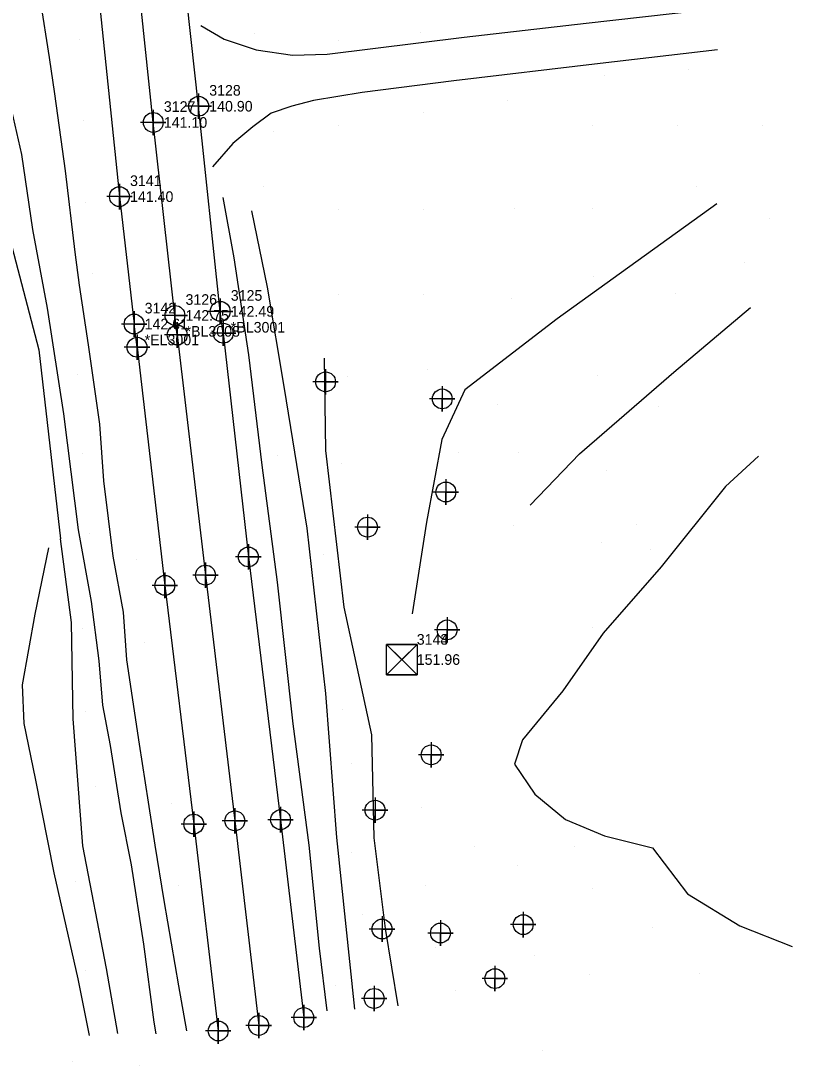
# Model space of a CAD drawing. Extents: x 2312183 to 2312663, y 819676 to 820746.
# Drawn here: x 2312471.4 to 2312653.3, y 819694.7 to 819940.8 of the extents above; entities that cross this region are included whole.
import ezdxf

# ---------------------------------------------------------------- set-up
doc = ezdxf.new("R2010")
doc.units = 0
for name, color, linetype in [('CTL Bench Mark CELL', 7, 'Continuous'), ('CTL Bench Mark Cogo Elevation', 7, 'Continuous'), ('CTL Bench Mark Cogo Number', 7, 'Continuous'), ('Exist DTM Crownline', 7, 'Continuous'), ('Exist DTM Crownline Cogo Comment', 7, 'Continuous'), ('Exist DTM Crownline Cogo Elevation', 7, 'Continuous'), ('Exist DTM Crownline Cogo Number', 7, 'Continuous'), ('Exist DTM Crownline Cogo Point CELL', 7, 'Continuous'), ('Exist DTM Regular Point CELL', 7, 'Continuous'), ('Exist Roads EOP', 7, 'Continuous'), ('Exist Roads EOP Cogo Comment', 7, 'Continuous'), ('Exist Roads EOP Cogo Elevation', 7, 'Continuous'), ('Exist Roads EOP Cogo Number', 7, 'Continuous'), ('Exist Roads EOP Cogo Point CELL', 7, 'Continuous'), ('PH Exist DTM Breakline', 7, 'Continuous'), ('PH Exist DTM Point', 7, 'Continuous')]:
    doc.layers.add(name, color=color, linetype=linetype)

msp = doc.modelspace()

# ---------------------------------------------------------------- linework, layer by layer
at = {"layer": 'CTL Bench Mark CELL'}
for p, q in [((2312561.27, 819790.29), (2312561.27, 819790.29)), ((2312561.27, 819790.29), (2312561.27, 819790.29)), ((2312561.27, 819790.28), (2312561.27, 819790.28)), ((2312561.27, 819790.28), (2312561.27, 819790.28))]:
    msp.add_line(p, q, dxfattribs=at)
for points in [[(2312557.67, 819793.87), (2312564.86, 819793.87), (2312564.86, 819786.69), (2312557.67, 819786.69)], [(2312557.67, 819793.87), (2312564.86, 819793.87), (2312564.86, 819786.68), (2312557.67, 819786.68)], [(2312557.67, 819793.87), (2312564.86, 819793.87), (2312564.86, 819786.69), (2312557.67, 819786.69)], [(2312557.67, 819793.87), (2312564.86, 819793.87), (2312564.86, 819786.68), (2312557.67, 819786.68)]]:
    msp.add_lwpolyline(points, close=True, dxfattribs=at)
for points in [[(2312564.86, 819793.87), (2312557.67, 819786.69), (2312561.26, 819790.28), (2312564.86, 819786.69), (2312557.67, 819793.87)], [(2312561.26, 819790.28), (2312564.86, 819793.87), (2312557.67, 819793.87), (2312561.26, 819790.28)], [(2312564.86, 819793.87), (2312557.67, 819786.68), (2312561.26, 819790.28), (2312564.86, 819786.68), (2312557.67, 819793.87)], [(2312561.26, 819790.28), (2312564.86, 819793.87), (2312557.67, 819793.87), (2312561.26, 819790.28)], [(2312564.86, 819793.87), (2312557.67, 819786.69), (2312561.26, 819790.28), (2312564.86, 819786.69), (2312557.67, 819793.87)], [(2312561.26, 819790.28), (2312564.86, 819793.87), (2312557.67, 819793.87), (2312561.26, 819790.28)], [(2312564.86, 819793.87), (2312557.67, 819786.68), (2312561.26, 819790.28), (2312564.86, 819786.68), (2312557.67, 819793.87)], [(2312561.26, 819790.28), (2312564.86, 819793.87), (2312557.67, 819793.87), (2312561.26, 819790.28)], [(2312561.26, 819790.28), (2312557.67, 819786.69), (2312564.86, 819786.69), (2312561.26, 819790.28)], [(2312561.26, 819790.28), (2312557.67, 819786.68), (2312564.86, 819786.68), (2312561.26, 819790.28)], [(2312561.26, 819790.28), (2312557.67, 819786.69), (2312564.86, 819786.69), (2312561.26, 819790.28)], [(2312561.26, 819790.28), (2312557.67, 819786.68), (2312564.86, 819786.68), (2312561.26, 819790.28)]]:
    msp.add_lwpolyline(points, dxfattribs=at)
at = {"layer": 'Exist DTM Crownline'}
for points in [[(2312507.73, 819871.39), (2312502.62, 819916.87), (2312496.97, 819970.94), (2312491.86, 820021.16), (2312483.41, 820106.75)], [(2312508.27, 819866.79), (2312507.73, 819871.39)], [(2312508.27, 819866.79), (2312514.94, 819810.18), (2312521.86, 819752.27), (2312527.49, 819704.05)]]:
    msp.add_lwpolyline(points, dxfattribs=at)
at = {"layer": 'Exist DTM Crownline Cogo Point CELL'}
for points in [[(2312502.62, 819919.87), (2312502.62, 819913.87), (2312502.62, 819916.87), (2312505.62, 819916.87), (2312499.62, 819916.87)], [(2312502.62, 819919.87), (2312502.62, 819913.87), (2312502.62, 819916.87), (2312505.62, 819916.87), (2312499.62, 819916.87)], [(2312507.73, 819874.39), (2312507.73, 819868.39), (2312507.73, 819871.39), (2312510.73, 819871.39), (2312504.73, 819871.39)], [(2312507.73, 819874.39), (2312507.73, 819868.39), (2312507.73, 819871.39), (2312510.73, 819871.39), (2312504.73, 819871.39)], [(2312508.27, 819869.79), (2312508.27, 819863.79), (2312508.27, 819866.79), (2312511.27, 819866.79), (2312505.27, 819866.79)], [(2312514.94, 819813.18), (2312514.94, 819807.18), (2312514.94, 819810.18), (2312517.94, 819810.18), (2312511.94, 819810.18)], [(2312521.86, 819755.27), (2312521.86, 819749.27), (2312521.86, 819752.27), (2312524.86, 819752.27), (2312518.86, 819752.27)], [(2312527.49, 819707.05), (2312527.49, 819701.05), (2312527.49, 819704.05), (2312530.49, 819704.05), (2312524.49, 819704.05)]]:
    msp.add_lwpolyline(points, dxfattribs=at)
for centre in [(2312502.62, 819916.87), (2312502.62, 819916.87), (2312507.73, 819871.39), (2312507.73, 819871.39), (2312508.27, 819866.79), (2312514.94, 819810.18), (2312521.86, 819752.27), (2312527.49, 819704.05)]:
    msp.add_circle(centre, 2.34, dxfattribs=at)
at = {"layer": 'Exist DTM Regular Point CELL'}
for points in [[(2312543.27, 819858.74), (2312543.27, 819852.74), (2312543.27, 819855.74), (2312546.27, 819855.74), (2312540.27, 819855.74)], [(2312570.79, 819854.71), (2312570.79, 819848.71), (2312570.79, 819851.71), (2312573.79, 819851.71), (2312567.79, 819851.71)], [(2312571.64, 819832.77), (2312571.64, 819826.77), (2312571.64, 819829.77), (2312574.64, 819829.77), (2312568.64, 819829.77)], [(2312553.15, 819824.5), (2312553.15, 819818.5), (2312553.15, 819821.5), (2312556.15, 819821.5), (2312550.15, 819821.5)], [(2312571.93, 819800.27), (2312571.93, 819794.27), (2312571.93, 819797.27), (2312574.93, 819797.27), (2312568.93, 819797.27)], [(2312568.18, 819770.83), (2312568.18, 819764.83), (2312568.18, 819767.83), (2312571.18, 819767.83), (2312565.18, 819767.83)], [(2312554.93, 819757.79), (2312554.93, 819751.79), (2312554.93, 819754.79), (2312557.93, 819754.79), (2312551.93, 819754.79)], [(2312589.89, 819730.81), (2312589.89, 819724.81), (2312589.89, 819727.81), (2312592.89, 819727.81), (2312586.89, 819727.81)], [(2312556.58, 819729.77), (2312556.58, 819723.77), (2312556.58, 819726.77), (2312559.58, 819726.77), (2312553.58, 819726.77)], [(2312570.36, 819728.83), (2312570.36, 819722.83), (2312570.36, 819725.83), (2312573.36, 819725.83), (2312567.36, 819725.83)], [(2312583.2, 819718.09), (2312583.2, 819712.09), (2312583.2, 819715.09), (2312586.2, 819715.09), (2312580.2, 819715.09)], [(2312554.72, 819713.41), (2312554.72, 819707.41), (2312554.72, 819710.41), (2312557.72, 819710.41), (2312551.72, 819710.41)]]:
    msp.add_lwpolyline(points, dxfattribs=at)
for centre in [(2312543.27, 819855.74), (2312570.79, 819851.71), (2312571.64, 819829.77), (2312553.15, 819821.5), (2312571.93, 819797.27), (2312568.18, 819767.83), (2312554.93, 819754.79), (2312589.89, 819727.81), (2312556.58, 819726.77), (2312570.36, 819725.83), (2312583.2, 819715.09), (2312554.72, 819710.41)]:
    msp.add_circle(centre, 2.34, dxfattribs=at)
at = {"layer": 'Exist Roads EOP'}
for points in [[(2312518.41, 819872.35), (2312513.32, 819920.69), (2312507.89, 819970.07), (2312502.32, 820023.24), (2312497.48, 820069.17), (2312493.43, 820108.42), (2312471.82, 820106.17), (2312475.2, 820073.59), (2312480.64, 820032.66), (2312484.77, 819994.6), (2312489.93, 819944.86), (2312494.64, 819899.39), (2312498.09, 819869.36)], [(2312519.12, 819867.2), (2312518.41, 819872.35)], [(2312498.79, 819863.89), (2312498.09, 819869.36)], [(2312519.12, 819867.2), (2312525.05, 819814.47), (2312532.65, 819752.54), (2312538.11, 819705.91)], [(2312498.79, 819863.89), (2312505.36, 819807.77), (2312512.17, 819751.51), (2312517.94, 819702.75)]]:
    msp.add_lwpolyline(points, dxfattribs=at)
at = {"layer": 'Exist Roads EOP Cogo Point CELL'}
for points in [[(2312513.32, 819923.69), (2312513.32, 819917.69), (2312513.32, 819920.69), (2312516.32, 819920.69), (2312510.32, 819920.69)], [(2312513.32, 819923.69), (2312513.32, 819917.69), (2312513.32, 819920.69), (2312516.32, 819920.69), (2312510.32, 819920.69)], [(2312513.32, 819923.69), (2312513.32, 819917.69), (2312513.32, 819920.69), (2312516.32, 819920.69), (2312510.32, 819920.69)], [(2312494.64, 819902.39), (2312494.64, 819896.39), (2312494.64, 819899.39), (2312497.64, 819899.39), (2312491.64, 819899.39)], [(2312494.64, 819902.39), (2312494.64, 819896.39), (2312494.64, 819899.39), (2312497.64, 819899.39), (2312491.64, 819899.39)], [(2312494.64, 819902.39), (2312494.64, 819896.39), (2312494.64, 819899.39), (2312497.64, 819899.39), (2312491.64, 819899.39)], [(2312518.41, 819875.35), (2312518.41, 819869.35), (2312518.41, 819872.35), (2312521.41, 819872.35), (2312515.41, 819872.35)], [(2312518.41, 819875.35), (2312518.41, 819869.35), (2312518.41, 819872.35), (2312521.41, 819872.35), (2312515.41, 819872.35)], [(2312518.41, 819875.35), (2312518.41, 819869.35), (2312518.41, 819872.35), (2312521.41, 819872.35), (2312515.41, 819872.35)], [(2312498.09, 819872.36), (2312498.09, 819866.36), (2312498.09, 819869.36), (2312501.09, 819869.36), (2312495.09, 819869.36)], [(2312498.09, 819872.36), (2312498.09, 819866.36), (2312498.09, 819869.36), (2312501.09, 819869.36), (2312495.09, 819869.36)], [(2312498.09, 819872.36), (2312498.09, 819866.36), (2312498.09, 819869.36), (2312501.09, 819869.36), (2312495.09, 819869.36)], [(2312519.12, 819870.2), (2312519.12, 819864.2), (2312519.12, 819867.2), (2312522.12, 819867.2), (2312516.12, 819867.2)], [(2312498.79, 819866.89), (2312498.79, 819860.89), (2312498.79, 819863.89), (2312501.79, 819863.89), (2312495.79, 819863.89)], [(2312525.05, 819817.47), (2312525.05, 819811.47), (2312525.05, 819814.47), (2312528.05, 819814.47), (2312522.05, 819814.47)], [(2312505.36, 819810.77), (2312505.36, 819804.77), (2312505.36, 819807.77), (2312508.36, 819807.77), (2312502.36, 819807.77)], [(2312532.65, 819755.54), (2312532.65, 819749.54), (2312532.65, 819752.54), (2312535.65, 819752.54), (2312529.65, 819752.54)], [(2312512.17, 819754.51), (2312512.17, 819748.51), (2312512.17, 819751.51), (2312515.17, 819751.51), (2312509.17, 819751.51)], [(2312538.11, 819708.91), (2312538.11, 819702.91), (2312538.11, 819705.91), (2312541.11, 819705.91), (2312535.11, 819705.91)], [(2312517.94, 819705.75), (2312517.94, 819699.75), (2312517.94, 819702.75), (2312520.94, 819702.75), (2312514.94, 819702.75)]]:
    msp.add_lwpolyline(points, dxfattribs=at)
for centre in [(2312513.32, 819920.69), (2312513.32, 819920.69), (2312513.32, 819920.69), (2312494.64, 819899.39), (2312494.64, 819899.39), (2312494.64, 819899.39), (2312518.41, 819872.35), (2312518.41, 819872.35), (2312518.41, 819872.35), (2312498.09, 819869.36), (2312498.09, 819869.36), (2312498.09, 819869.36), (2312519.12, 819867.2), (2312498.79, 819863.89), (2312525.05, 819814.47), (2312505.36, 819807.77), (2312532.65, 819752.54), (2312512.17, 819751.51), (2312538.11, 819705.91), (2312517.94, 819702.75)]:
    msp.add_circle(centre, 2.34, dxfattribs=at)
at = {"layer": 'PH Exist DTM Breakline'}
for points in [[(2312503.34, 819702.08), (2312502.81, 819704.79), (2312500.39, 819723.23), (2312497.46, 819741.87), (2312495.03, 819754.19), (2312492.55, 819770.03), (2312490.74, 819779.57), (2312489.87, 819790), (2312488.08, 819803.96), (2312484.99, 819820.88), (2312481.53, 819848.23), (2312477.71, 819873.12), (2312474.2, 819891.66), (2312471.62, 819909.28), (2312467.7, 819926.63), (2312464.56, 819938.8), (2312459.08, 819971.31), (2312454.5, 819994.88), (2312448.74, 820025.26), (2312445.38, 820042.56), (2312443.53, 820058.78), (2312443.06, 820065.38)], [(2312475.94, 819945.72), (2312478.04, 819932.21), (2312479.33, 819923.64), (2312481.85, 819905.43), (2312484.14, 819886.33), (2312485.14, 819878.51), (2312487.3, 819864.49), (2312489.92, 819845.75), (2312490.89, 819832.44), (2312493.07, 819814.69), (2312495.53, 819801.48), (2312496.3, 819790.22), (2312499.27, 819770.31), (2312501.44, 819756.67), (2312502.97, 819746.54), (2312505.08, 819733.48), (2312508.59, 819713.4), (2312510.42, 819702.8)], [(2312513.82, 819939.75), (2312519.38, 819936.51), (2312526.86, 819933.99), (2312535.44, 819932.71), (2312543.63, 819933), (2312575.99, 819937.01), (2312604.73, 819940.27), (2312632.01, 819943.32)], [(2312459.33, 819939.76), (2312463.34, 819926.83), (2312466, 819899.69), (2312475.66, 819863.29), (2312480.7, 819818.73)], [(2312635.69, 819933.98), (2312608, 819930.74), (2312573.51, 819926.67), (2312551.9, 819923.9), (2312540.45, 819922.01), (2312535.34, 819920.69), (2312530.41, 819919.06), (2312526.08, 819915.85), (2312521.4, 819911.89), (2312516.56, 819906.43)], [(2312543.62, 819707.49), (2312541.85, 819722.25), (2312539.38, 819746.51), (2312535.63, 819775.13), (2312531.9, 819808.53), (2312528.29, 819836.09), (2312525.15, 819862.12), (2312521.68, 819884.93), (2312519.11, 819899.15)], [(2312635.54, 819897.68), (2312597.88, 819870.59), (2312576.13, 819853.82), (2312570.68, 819842.15), (2312567.05, 819822.67), (2312563.71, 819801.05)], [(2312550.2, 819707.92), (2312545.9, 819748.34), (2312543.36, 819782.29), (2312538.91, 819821.24), (2312533.6, 819854.2), (2312529.6, 819878.04), (2312525.89, 819896.02)], [(2312591.56, 819826.65), (2312603.18, 819838.76), (2312625.39, 819858.01), (2312643.46, 819873.26)], [(2312560.4, 819708.65), (2312557.38, 819726.86), (2312554.73, 819748.27), (2312554.19, 819772.54), (2312547.63, 819802.67), (2312543.34, 819839.59), (2312543.02, 819861.34)], [(2312645.35, 819838.22), (2312637.62, 819831.05), (2312622.42, 819812.15), (2312608.76, 819796.48), (2312599.25, 819782.91), (2312589.69, 819771.34), (2312587.83, 819765.59), (2312592.64, 819758.56), (2312599.82, 819752.58), (2312609.07, 819748.72), (2312620.35, 819745.93), (2312628.62, 819735.09), (2312640.97, 819727.56), (2312653.31, 819722.66)], [(2312494.25, 819702.19), (2312491.55, 819717.46), (2312485.99, 819746.36), (2312483.74, 819776.31), (2312483.32, 819799.04), (2312480.7, 819818.73)], [(2312477.91, 819816.65), (2312474.7, 819800.98), (2312471.67, 819784.33), (2312472.08, 819775.22), (2312474.73, 819762.24), (2312479.18, 819740.01), (2312484.83, 819715.02), (2312487.49, 819701.71)]]:
    msp.add_lwpolyline(points, dxfattribs=at)
at = {"layer": 'PH Exist DTM Point'}
for p, q in [((2312526.46, 819937.92), (2312526.46, 819937.92)), ((2312565.7, 819938.18), (2312565.7, 819938.18)), ((2312485.16, 819936.45), (2312485.16, 819936.45)), ((2312546.32, 819936.25), (2312546.32, 819936.25)), ((2312609.12, 819927.84), (2312609.12, 819927.84)), ((2312628.76, 819929.28), (2312628.76, 819929.28)), ((2312586.26, 819922.08), (2312586.26, 819922.08)), ((2312486.1, 819917.25), (2312486.1, 819917.25)), ((2312566.32, 819919.17), (2312566.32, 819919.17)), ((2312531.05, 819914.81), (2312531.05, 819914.81)), ((2312546.32, 819916.25), (2312546.32, 819916.25)), ((2312606.31, 819916.27), (2312606.31, 819916.27)), ((2312626.32, 819916.25), (2312626.32, 819916.25)), ((2312646.33, 819916.24), (2312646.33, 819916.24)), ((2312528.61, 819901.66), (2312528.61, 819901.66)), ((2312630.7, 819901.77), (2312630.7, 819901.77)), ((2312486.59, 819898.02), (2312486.59, 819898.02)), ((2312546.32, 819896.25), (2312546.32, 819896.25)), ((2312566.29, 819896.36), (2312566.29, 819896.36)), ((2312587.76, 819896.67), (2312587.76, 819896.67)), ((2312606.23, 819896.53), (2312606.23, 819896.53)), ((2312647.98, 819894.33), (2312647.98, 819894.33)), ((2312642.01, 819883.77), (2312642.01, 819883.77)), ((2312488.18, 819881.19), (2312488.18, 819881.19)), ((2312606.43, 819880.46), (2312606.43, 819880.46)), ((2312546.32, 819876.25), (2312546.32, 819876.25)), ((2312566.31, 819876.28), (2312566.31, 819876.28)), ((2312587.2, 819875.32), (2312587.2, 819875.32)), ((2312625.77, 819876.44), (2312625.77, 819876.44)), ((2312567.25, 819858.54), (2312567.25, 819858.54)), ((2312484.86, 819857.39), (2312484.86, 819857.39)), ((2312548.49, 819856.95), (2312548.49, 819856.95)), ((2312607.39, 819857.33), (2312607.39, 819857.33)), ((2312583.78, 819850.42), (2312583.78, 819850.42)), ((2312621.69, 819849.84), (2312621.69, 819849.84)), ((2312485.96, 819838.95), (2312485.96, 819838.95)), ((2312574.59, 819839.03), (2312574.59, 819839.03)), ((2312588.81, 819839.1), (2312588.81, 819839.1)), ((2312531.88, 819838.32), (2312531.88, 819838.32)), ((2312547.06, 819836.5), (2312547.06, 819836.5)), ((2312609.63, 819834.76), (2312609.63, 819834.76)), ((2312587.65, 819821.95), (2312587.65, 819821.95)), ((2312616.59, 819822.05), (2312616.59, 819822.05)), ((2312487.59, 819820.05), (2312487.59, 819820.05)), ((2312608.35, 819817.94), (2312608.35, 819817.94)), ((2312542.82, 819815.12), (2312542.82, 819815.12)), ((2312619.79, 819816.17), (2312619.79, 819816.17)), ((2312498.63, 819813.76), (2312498.63, 819813.76)), ((2312485.86, 819797.67), (2312485.86, 819797.67)), ((2312606.22, 819797.88), (2312606.22, 819797.88)), ((2312500.58, 819794.33), (2312500.58, 819794.33)), ((2312486.7, 819778.05), (2312486.7, 819778.05)), ((2312547.19, 819778.58), (2312547.19, 819778.58)), ((2312549.29, 819765.82), (2312549.29, 819765.82)), ((2312489.01, 819760.26), (2312489.01, 819760.26)), ((2312506.83, 819756.41), (2312506.83, 819756.41)), ((2312565.93, 819755.47), (2312565.93, 819755.47)), ((2312578.3, 819746.28), (2312578.3, 819746.28)), ((2312602.04, 819746.31), (2312602.04, 819746.31)), ((2312549.49, 819744.78), (2312549.49, 819744.78)), ((2312588.47, 819741.76), (2312588.47, 819741.76)), ((2312484.34, 819738.06), (2312484.34, 819738.06)), ((2312508.57, 819736.97), (2312508.57, 819736.97)), ((2312566.91, 819736.92), (2312566.91, 819736.92)), ((2312606.32, 819736.24), (2312606.32, 819736.24)), ((2312552.08, 819730.28), (2312552.08, 819730.28)), ((2312620.42, 819727.17), (2312620.42, 819727.17)), ((2312569.09, 819722.41), (2312569.09, 819722.41)), ((2312592.65, 819720.44), (2312592.65, 819720.44)), ((2312486.52, 819716.93), (2312486.52, 819716.93)), ((2312605.51, 819716.07), (2312605.51, 819716.07)), ((2312631.51, 819716.27), (2312631.51, 819716.27)), ((2312545.53, 819713.42), (2312545.53, 819713.42)), ((2312574, 819712.35), (2312574, 819712.35)), ((2312483.6, 819695.65), (2312483.6, 819695.65)), ((2312594.49, 819698.03), (2312594.49, 819698.03)), ((2312499.27, 819694.7), (2312499.27, 819694.7))]:
    msp.add_line(p, q, dxfattribs=at)

# ---------------------------------------------------------------- texts
at = {"layer": 'CTL Bench Mark Cogo Elevation'}
for p in [(2312564.77, 819789.04), (2312564.77, 819789.03)]:
    msp.add_text('151.96', height=2.5, dxfattribs=at).set_placement(p)
at = {"layer": 'CTL Bench Mark Cogo Number'}
for s, p in [('3143', (2312564.77, 819793.79)), ('3144', (2312564.77, 819793.78))]:
    msp.add_text(s, height=2.5, dxfattribs=at).set_placement(p)
at = {"layer": 'Exist DTM Crownline Cogo Comment'}
msp.add_text('*BL3008', height=2.5, dxfattribs=at).set_placement((2312510.23, 819866.39))
at = {"layer": 'Exist DTM Crownline Cogo Elevation'}
for s, p in [('141.10', (2312505.12, 819915.62)), ('142.75', (2312510.23, 819870.14))]:
    msp.add_text(s, height=2.5, dxfattribs=at).set_placement(p)
at = {"layer": 'Exist DTM Crownline Cogo Number'}
for s, p in [('3127', (2312505.12, 819919.37)), ('3126', (2312510.23, 819873.89))]:
    msp.add_text(s, height=2.5, dxfattribs=at).set_placement(p)
at = {"layer": 'Exist Roads EOP Cogo Comment'}
for s, p in [('*BL3001', (2312520.91, 819867.35)), ('*EL3001', (2312500.59, 819864.36))]:
    msp.add_text(s, height=2.5, dxfattribs=at).set_placement(p)
at = {"layer": 'Exist Roads EOP Cogo Elevation'}
for s, p in [('140.90', (2312515.82, 819919.44)), ('141.40', (2312497.14, 819898.14)), ('142.49', (2312520.91, 819871.1)), ('142.61', (2312500.59, 819868.11))]:
    msp.add_text(s, height=2.5, dxfattribs=at).set_placement(p)
at = {"layer": 'Exist Roads EOP Cogo Number'}
for s, p in [('3128', (2312515.82, 819923.19)), ('3141', (2312497.14, 819901.89)), ('3125', (2312520.91, 819874.85)), ('3142', (2312500.59, 819871.86))]:
    msp.add_text(s, height=2.5, dxfattribs=at).set_placement(p)

doc.saveas('drawing.dxf')
